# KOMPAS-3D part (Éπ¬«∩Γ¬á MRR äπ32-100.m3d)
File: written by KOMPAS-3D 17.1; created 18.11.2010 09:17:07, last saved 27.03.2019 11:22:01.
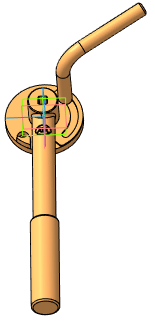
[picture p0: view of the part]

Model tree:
1. Плоскость XY
2. Плоскость ZX
3. Плоскость ZY
4. Ось X
5. Ось Y
6. Ось Z
7. Начало координат
8. Операция без истории:2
